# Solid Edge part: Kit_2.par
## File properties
Username: bmolnar
Dokumentum tartalom típus: 0
Author: bmolnar
Last saved by: bmolnar
Revision: 76
Sűrűség: 0,000 kg/m^3
Pontosság: 0,990
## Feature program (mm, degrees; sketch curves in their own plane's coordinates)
base feature "unnamed BaseFeature 1"
sketch for "unnamed Hole 1" plane through (-28.25, -28.25, 94) normal (0, 0, 1) x-axis (0, 1, 0)
  hole centre (0, 0) bore radius 3.3235
hole "unnamed Hole 1" through
sketch for "unnamed Hole 2" plane through (-28.25, -28.25, 94) normal (0, 0, 1) x-axis (0, 1, 0)
  hole centre (56.5, 0) bore radius 3.3235
hole "unnamed Hole 2" through
sketch for "unnamed Hole 3" plane through (-28.25, -28.25, 94) normal (0, 0, 1) x-axis (0, 1, 0)
  hole centre (0, -56.5) bore radius 3.3235
hole "unnamed Hole 3" through
sketch for "unnamed Hole 4" plane through (-28.25, -28.25, 94) normal (0, 0, 1) x-axis (0, 1, 0)
  hole centre (56.5, -56.5) bore radius 3.3235
hole "unnamed Hole 4" through
pattern "unnamed Pattern 1" of "unnamed Hole 1", "unnamed Hole 2", "unnamed Hole 3", "unnamed Hole 4"
sketch for "Furat_5" plane through (-38.44, 0, 92.125) normal (-0.999962, 0, 0.008727) x-axis (0, 1, 0)
  hole centre (0, 0.6247) bore radius 4.283
hole "Furat_5" nominal diameter 9.728 finite  ThreadDepth = 10 mm
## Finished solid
Body 1: solid body, 308 faces, 758 edges, 465 vertices.
  Faces by surface: plane 141, cylinder 75, swept 61, cone 20, torus 10, spline 1
  Edges by curve: line 431, circle 154, spline 126, ellipse 30, curve on surface 17
Bounding box of the edges (mm; curved faces can reach further): 77.000 x 77.000 x 13.750, from (-38.5, -38.5, 85.25) to (38.5, 38.5, 99).
Cylindrical faces by radius (mm): R0.2 x48, R0.2008 x2, R0.2009 x2, R0.402 x1, R0.4899 x1, R3.3235 x4, R4.283 x1, R4.9 x4, R5.15 x4, R5.25 x4, R8.27 x1, R8.85 x1, R9 x1, R10.25 x1
Conical faces (half-angle, radius in mm at the cone's reference point): 0.5 deg R12 x4, 0.5 deg R13.5 x2, 7 deg R9.5925 x1, 14 deg R8.135 x1, 14 deg R8.4811 x1, 17 deg R8.135 x1, 23 deg R8.829 x1, 42.5 deg R8.1233 x1, 45 deg R3.6735 x4, 45 deg R9 x1, 84 deg R8.4608 x1, 85 deg R9.9463 x1, 87 deg R8.1765 x1
Toroidal faces (ring radius, tube radius in mm): R4.7 r0.2 x8, R8.8057 r0.2025 x1, R9.2522 r0.2925 x1
Planar faces by outward normal: +x 12, +y 13, +z 19, -x 14, -y 14, -z 1, oblique 68
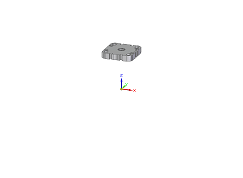
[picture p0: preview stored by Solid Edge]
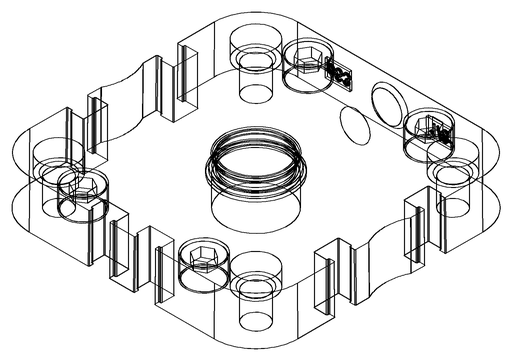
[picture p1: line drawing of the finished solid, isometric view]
